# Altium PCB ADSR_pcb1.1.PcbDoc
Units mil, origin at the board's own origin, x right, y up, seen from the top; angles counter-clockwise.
Board outline 3150 x 1575 mil, 2 copper layers (Top Layer, Bottom Layer); 39 components, 29 nets, 111 pads, 15 vias.
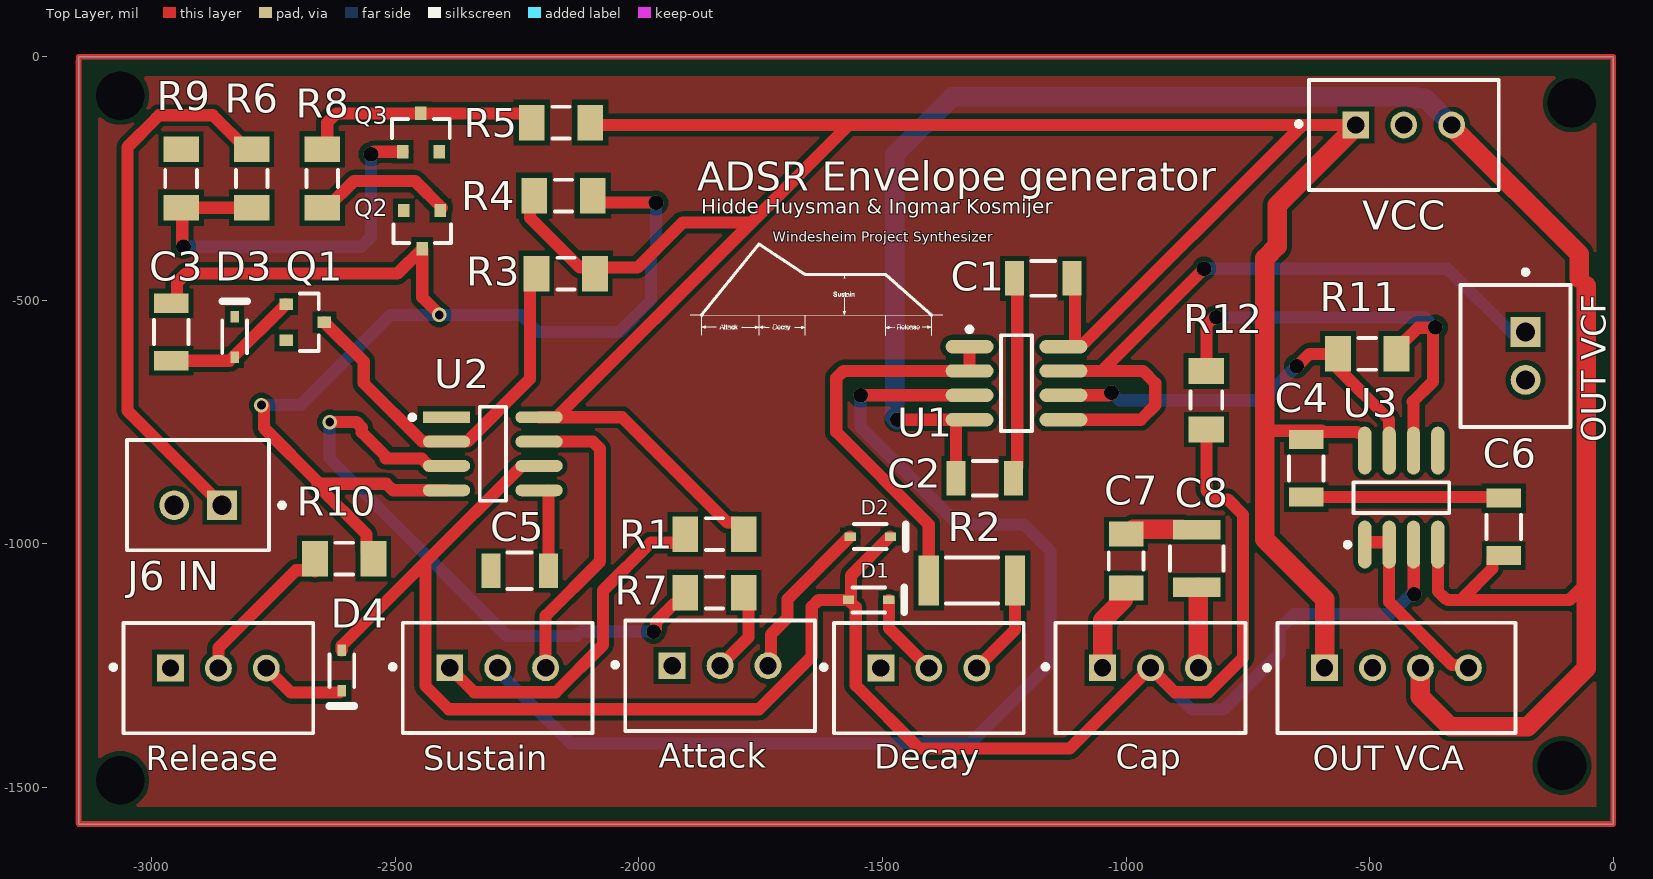
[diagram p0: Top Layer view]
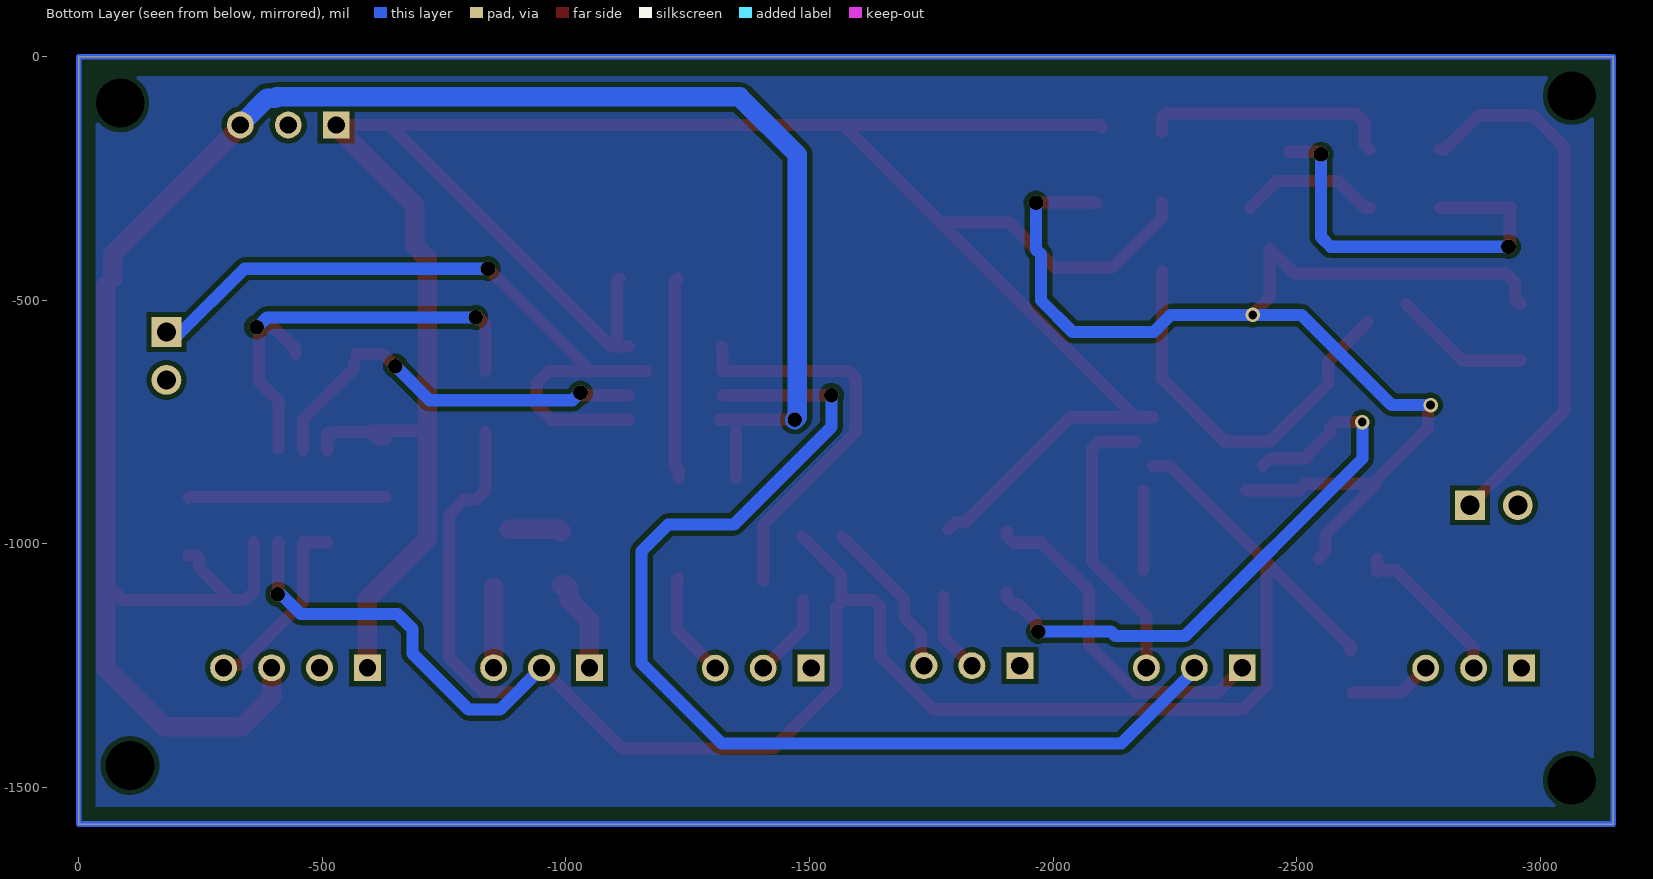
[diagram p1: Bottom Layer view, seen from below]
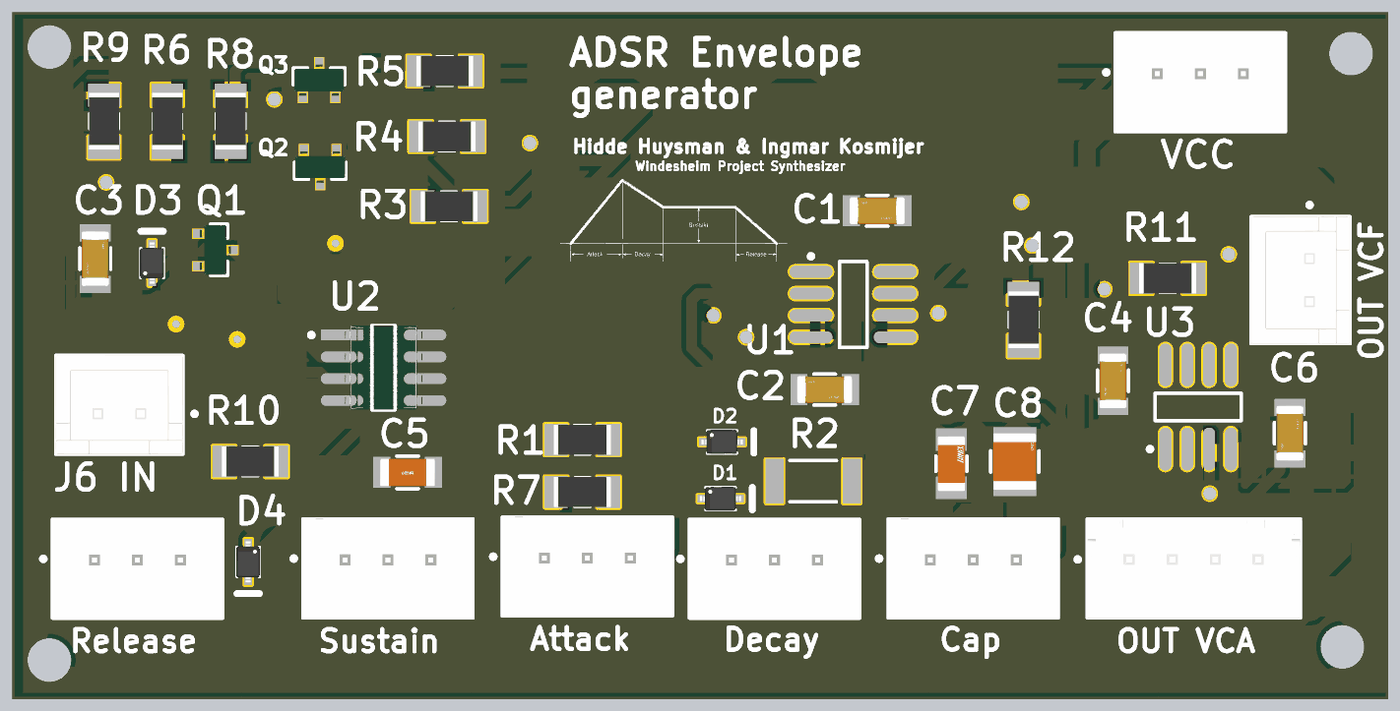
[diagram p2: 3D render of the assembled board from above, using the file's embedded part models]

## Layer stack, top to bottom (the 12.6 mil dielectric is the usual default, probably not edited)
Top Solder: solder mask 0.4, Solder Resist, Dk 3.5
Top Layer: signal copper 1.4
Dielectric 1: dielectric 12.6, FR-4, Dk 4.8
Bottom Layer: signal copper 1.4
Bottom Solder: solder mask 0.4, Solder Resist, Dk 3.5

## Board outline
-3150,-1575 -3150,0 0,0 0,-1575

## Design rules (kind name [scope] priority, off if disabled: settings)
Clearance [All] p1: gap=10 ignorepadtopadclearanceinfootprint=FALSE except(0: Arc-Hole Track-Hole SMDPad-Hole THPad-Hole Via-Hole Fill-Hole Poly-Hole Region-Hole Text-Hole)
HoleSize [IsVia] p1: absolutevalues=TRUE maxlimit=30 minlimit=12 maxpercent=80.000 minpercent=20.000
PolygonConnect [All] p1: connectstyle=Relief reliefconductorwidth=10 reliefentries=4 polygonreliefangle="90 Angle" airgapwidth=10
RoutingVias [All] p1: holewidth=28 width=50 viastyle="Through Hole" minholewidth=28 minwidth=50 maxholewidth=28 maxwidth=50
SolderMaskExpansion [All] p1: expansion=4 istentingtop=FALSE
Width [All] p1: maxlimit=40 minlimit=12 preferedwidth=25 minimp=50.000000 maximp=50.000000 favimp=50.000000
29 further rules are at their usual default settings.

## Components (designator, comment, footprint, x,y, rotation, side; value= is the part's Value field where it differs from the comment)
Attack "B3B-XH-A(LF)(SN)" FP-B3B-XH-A_LF_SN-MFG -1833.43,-1270.67 r0 top (schematic designator "J5 A")
C1 "CC1206KRX7R9BB103" FP-CC1206-1_25-MFG -1170,-455 r0 top value="10 nF"
C2 "CC1206KRX7R9BB103" FP-CC1206-1_25-MFG -1290,-865 r0 top value="10 nF"
C3 "CC1206KRX7R9BB103" FP-CC1206-1_25-MFG -2960,-565 r270 top value="10 nF"
C4 "CC1206KRX7R9BB103" FP-CC1206-1_25-MFG -630,-845 r270 top value="10 nF"
C5 "CC1206KKX5R9BB106" FP-CC1206-FD-MFG -2245,-1055 r180 top
C6 "CC1206KRX7R9BB103" FP-CC1206-1_25-MFG -225,-965 r90 top value="10 nF"
C7 "1206YC224K4T2A" FP-1206-L_3_2_0_2-W_1_6_0-IPC_B -1000,-1035 r90 top
C8 "12105C475K4T2A" FP-1210-L_3_3_0_4-W_2_5_0-MFG -855,-1030 r90 top
Cap "B3B-XH-A(LF)(SN)" FP-B3B-XH-A_LF_SN-MFG -950,-1275 r0 top (schematic designator "J4 Cap")
D1 "1N4148WS" DIOD-SOD323-2-A_V -1528.46,-1115 r0 top
D2 "1N4148WS" DIOD-SOD323-2-A_V -1525,-985 r0 top
D3 "1N4148WS" DIOD-SOD323-2-A_V -2830,-575 r90 top
D4 "1N4148WS" DIOD-SOD323-2-A_V -2610,-1260 r270 top
Decay "B3B-XH-A(LF)(SN)" FP-B3B-XH-A_LF_SN-MFG -1405,-1275.67 r0 top (schematic designator "J2 D")
"J6 IN" "B2B-XH-A(LF)(SN)" FP-B2B-XH-A_LF_SN-MFG -2905,-900 r180 top
"OUT VCA" "B4B-XH-A(LF)(SN)" FP-B4B-XH-A_LF_SN-MFG -445,-1275 r180 top
"OUT VCF" "B2B-XH-A(LF)(SN)" FP-B2B-XH-A_LF_SN-MFG -200.67,-614.21 r270 top (schematic designator "J9 OUT VCF")
Q1 "BC847,215" FP-SOT23-MFG -2685,-545 r0 top
Q2 "BC847,215" FP-SOT23-MFG -2445,-355 r270 top
Q3 "BC847,215" FP-SOT23-MFG -2447.6,-155.63 r90 top
R1 "Resistor 100k +/-1% 1206 250 mW" RESC3216X60X45ML15T20 -1845,-980 r0 top value=4.7k
R2 "CRCW2010100RFKEF" RESC2010(5025)_L -1316.42,-1075 r180 top value=1k
R3 "Resistor 100k +/-1% 1206 250 mW" RESC3216X60X45ML15T20 -2150.04,-445 r0 top value=4.7k
R4 "Resistor 100k +/-1% 1206 250 mW" RESC3216X60X45ML15T20 -2154.96,-285 r180 top value=4.7k
R5 "Resistor 100k +/-1% 1206 250 mW" RESC3216X60X45ML15T20 -2160,-135 r0 top value=4.7k
R6 "Resistor 100k +/-1% 1206 250 mW" RESC3216X60X45ML15T20 -2795,-250 r90 top value=10k
R7 "Resistor 100k +/-1% 1206 250 mW" RESC3216X60X45ML15T20 -1844.96,-1100 r180 top value=100
R8 "Resistor 100k +/-1% 1206 250 mW" RESC3216X60X45ML15T20 -2650,-250 r90 top value=10k
R9 "Resistor 100k +/-1% 1206 250 mW" RESC3216X60X45ML15T20 -2940,-250 r270 top value=100k
R10 "Resistor 100k +/-1% 1206 250 mW" RESC3216X60X45ML15T20 -2605,-1030 r0 top value=100
R11 "Resistor 100k +/-1% 1206 250 mW" RESC3216X60X45ML15T20 -505,-610 r0 top value=3k
R12 "Resistor 100k +/-1% 1206 250 mW" RESC3216X60X45ML15T20 -835,-705 r270 top value=4.7k
Release "B3B-XH-A(LF)(SN)" FP-B3B-XH-A_LF_SN-MFG -2863.43,-1275.67 r0 top (schematic designator "J8 R")
Sustain "B3B-XH-A(LF)(SN)" FP-B3B-XH-A_LF_SN-MFG -2290,-1275 r0 top (schematic designator "J3 S")
U1 "AD8066ARZ-R7" ADI-R-8_M -1225,-670 r0 top
U2 "NE555DR" FP-D0008A-IPC_A -2300,-815 r0 top
U3 "AD8066ARZ-R7" ADI-R-8_M -435,-905 r90 top
VCC "B3B-XH-A(LF)(SN)" FP-B3B-XH-A_LF_SN-MFG -430,-160.67 r0 top (schematic designator J1)

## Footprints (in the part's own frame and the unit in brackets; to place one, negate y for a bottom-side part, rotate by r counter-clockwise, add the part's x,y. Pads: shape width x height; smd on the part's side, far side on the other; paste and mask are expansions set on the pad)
ADI-R-8_M [mm] "SOIC, 8-Leads, Body 4.9x3.9mm, Pitch 1.27mm, IPC Low Density"
  oval 2.5x0.7 smd: 1(-2.45,1.905) 2(-2.45,0.635) 3(-2.45,-0.635) 4(-2.45,-1.905) 5(2.45,-1.905) 6(2.45,-0.635) 7(2.45,0.635) 8(2.45,1.905)
  silkscreen extent -2.57,-2.5 0.8,2.93, body extent -2,-2.5 2,2.5, height 1.75
DIOD-SOD323-2-A_V [mm] "SOD-323, 2-Leads, Body 1.7x1.3mm, Lead Span 2.5mm"
  rect 0.59x0.45 smd: 1(-1.055,0) 2(1.055,0)
  silkscreen extent -0.85,-0.65 1.85,0.65, body extent -1.24,-0.7 1.24,0.7, height 1.2
FP-1206-L_3_2_0_2-W_1_6_0-IPC_B [mil]
  rect 51.36x71.11 smd paste+0 mask+0: 1(-55.15,0) 2(55.15,0)
  silkscreen extent -18,-36 18,36, body extent -91,-45 91,45, height 10
FP-1210-L_3_3_0_4-W_2_5_0-MFG [mm]
  rect 1x2.5 smd paste+0 mask+0: 1(-1.5,0) 2(1.5,0)
  silkscreen extent -0.62,-1.4 0.62,1.4, body extent -2.1,-1.5 2.1,1.5, height 0.25
FP-B2B-XH-A_LF_SN-MFG [mm]
  rect 1.55x1.55 hole 1 paste-2539.97 mask+0: 1(-1.25,0.525)
  round 1.55 hole 1 paste-2539.97 mask+0: 2(1.25,0.525)
  silkscreen extent -4.5,-2.87 3.7,2.88, body extent -3.8,-2.98 3.8,2.98, height 0.25
FP-B3B-XH-A_LF_SN-MFG [mm]
  rect 1.4x1.4 hole 0.9 paste-2539.97 mask+0: 1(-2.5,0.525)
  round 1.4 hole 0.9 paste-2539.97 mask+0: 2(0,0.525) 3(2.5,0.525)
  silkscreen extent -5.6,-2.87 4.95,2.88, body extent -5.05,-2.98 5.05,2.98, height 0.25
FP-B4B-XH-A_LF_SN-MFG [mm]
  rect 1.4x1.4 hole 0.9 paste-2539.97 mask+0: 1(3.75,-0.525)
  round 1.4 hole 0.9 paste-2539.97 mask+0: 2(1.25,-0.525) 3(-1.25,-0.525) 4(-3.75,-0.525)
  silkscreen extent -6.2,-2.88 6.87,2.87, body extent -6.3,-2.98 6.3,2.98, height 0.25
FP-CC1206-1_25-MFG [mm]
  rect 1x1.8 smd paste+0 mask+0: 1(-1.5,0) 2(1.5,0)
  silkscreen extent -0.62,-0.9 0.63,0.9, body extent -2.2,-1.25 2.2,1.25, height 0.25
FP-CC1206-FD-MFG [mm]
  rect 1x1.8 smd paste+0 mask+0: 1(-1.5,0) 2(1.5,0)
  silkscreen extent -0.62,-0.95 0.62,0.95, body extent -2.32,-1.38 2.32,1.38, height 0.25
FP-D0008A-IPC_A [mil]
  rect 97.21x24.49 smd paste+0 mask+0: 1(-95.02,75)
  rrect100% 97.21x24.49 smd paste+0 mask+0: 2(-95.02,25) 3(-95.02,-25) 4(-95.02,-75) 5(95.02,-75) 6(95.02,-25) 7(95.02,25) 8(95.02,75)
  silkscreen extent -170,-97 27,97, body extent -163,-116 163,116, height 10
FP-SOT23-MFG [mm]
  rect 0.7x0.6 smd paste-1000 mask+0: 1(-1,0.95) 2(-1,-0.95) 3(1,0)
  silkscreen extent -0.27,-1.5 0.7,1.5, body extent -1.5,-1.65 1.5,1.65, height 0.25
RESC2010(5025)_L [mm] "Chip Resistor, Body 5.0x2.5mm, IPC High Density"
  rect 1.05x2.6 smd: 1(-2.25,0) 2(2.25,0)
  silkscreen extent -1.35,-1.2 1.35,1.2, body extent -2.6,-1.35 2.6,1.35, height 0.71
RESC3216X60X45ML15T20 [mm] "Chip Resistor, 2-Leads, Body 3.3x1.75mm, IPC Low Density"
  rect 1.35x1.85 smd: 1(-1.525,0) 2(1.525,0)
  silkscreen extent -0.45,-0.82 0.45,0.82, body extent -1.65,-0.87 1.65,0.87, height 0.6

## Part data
Attack Cap Decay Release Sustain VCC: library part CMP-17439-000014-3, "CONN HEADER VERT 3POS 2.5MM", Color=Natural, Contact Resistance=20mR, Current Rating=3A, Flammability Rating="UL94 V-0", Housing Color=White, Insulation Resistance=1GR, Max Operating Temperature=85°C, Max Voltage Rating (AC)=250V, Min Operating Temperature=-25°C
C1 C2 C3 C4 C6: library part CMP-1037-03511-2, "CAP CER 10000PF 50V X7R 1206", Capacitance="10 nF", Manufacturer=Yageo, Package=CC1206-1.25, Temperature="-55°C to +125°C", Temperature Characteristic=X7R, Temperature Coefficient=15%, Temperature Range High=+125°C, Temperature Range Low=-55°C, Tolerance=0.1, Voltage Rating="50 V"
C5: library part CMP-03422-001420-1, "CAP CER 10UF 50V X5R 1206", Capacitance=10uF, Case/Package=1206, Dielectric=X5R, Max Operating Temperature=85°C, Min Operating Temperature=-55°C, Tolerance=10%, Voltage Rating=50V
C7: library part CMP-04427-019066-1, "Automotive Ceramic Capacitor, 1206, 220nF, 10%, X7R, 15%, 16V", Capacitance=220nF, Case/Package=1206, Dielectric=X7R, Max Operating Temperature=125°C, Min Operating Temperature=-55°C, Tolerance=10%, Voltage Rating (DC)=16V
C8: library part CMP-04427-006002-1, "Automotive Ceramic Capacitor, 1210, 4.7uF, 10%, X7R, 15%, 50V", Capacitance=4.7uF, Case Code (Imperial)=1210, Case Code (Metric)=3225, Dielectric=X7R, Max Operating Temperature=125°C, Min Operating Temperature=-55°C, Package Quantity=1000, Ratings=AEC-Q200, Tolerance=10%, Voltage Rating=50V
D1 D2 D3 D4: library part CMP-004-00002-2, "Fast Switching Diode, 75 V, 0.3 A, -65 to 150 degC, 2-Pin SOD323, RoHS, Tape and Reel", Case/Package=SOD, Forward Current=300mA, Forward Voltage=1.25V, Manufacturer="Diodes Inc", Max Operating Temperature=150°C, Max Surge Current=2A, Min Operating Temperature=-65°C, Package Description="2-Pin Small Outline Diode, Body 1.7 x 1.3 mm", Package Quantity=3000, Package Reference=SOD323-2, Peak Reverse Current=1uA
"J6 IN" "OUT VCF": library part CMP-2000-05888-3, "CONN HEADER VERT 2POS 2.5MM", Color=Natural, Contact Resistance=20mR, Current Rating=3A, Housing Color=White, Insulation Resistance=1GR, Max Operating Temperature=85°C, Max Voltage Rating (AC)=250V, Min Operating Temperature=-25°C
"OUT VCA": library part CMP-17439-000250-1, "CONN HEADER VERT 4POS 2.5MM", Color=Natural, Contact Resistance=20mR, Current Rating=3A, Flammability Rating="UL94 V-0", Housing Color=White, Insulation Resistance=1GR, Max Operating Temperature=85°C, Max Voltage Rating (AC)=250V, Min Operating Temperature=-25°C, Package Quantity=500
Q1 Q2 Q3: library part CMP-14406-000009-1, "TRANS NPN 45V 0.1A SOT23", Ambient Temperature Range High=+150°C, Ambient Temperature Range Low=-65°C, Collector Base Voltage=50V, Collector Emitter Breakdown Voltage=45V, Collector Emitter Saturation Voltage=200mV, Emitter Base Voltage=6V, Manufacturer=Nexperia, Max Collector Current=100mA, Package=SOT23, Power Dissipation=250mW, Temperature="to +150°C"
R1 R3 R4 R5 R6 R7 R8 R9 R10 R11 R12: library part CMP-009-00025-5, "Chip Resistor, 100 KOhm, +/- 1%, 0.25 W, -55 to 155 degC, 1206 (3216 Metric)", Case/Package=1206, Max Operating Temperature=155°C, Min Operating Temperature=-55°C, Power=250mW, Tolerance=1%, Voltage Rating=200V
R2: library part CMP-009-00178-1, "Fixed Resistor, Metal Glaze/thick Film, 0.75W, 100ohm, 400V, 1% +/-Tol, 100ppm/Cel, Surface Mount, 2010", Case/Package=2010, Max Operating Temperature=155°C, Min Operating Temperature=-55°C, Power=750mW, Tolerance=1%
U1 U3: library part CMP-0384-01346-2, "Double Channel Low Power Operational Amplifier, 145 MHz BW, 180 V/us SR, Industrial, 8-pin SOIC (R-8), Reel", Amplifiers Per Package=2, Generic Part Number=AD8066, Input Bias Current=2pA, Input Offset Voltage=400uV, Manufacturer="Analog Devices"
U2: library part CMP-1685-00007-2, "IC OSC SGL TIMER 100KHZ 8-SOIC", Case/Package=SOIC, Frequency=100kHz, High Level Output Current=-200mA, Low Level Output Current=200mA, Max Operating Temperature=70°C, Max Supply Voltage=16V, Min Operating Temperature=0°C, Min Supply Voltage=4.5V, Operating Supply Current=10mA, Package Quantity=2500, Quiescent Current=15mA

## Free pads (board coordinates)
  round 60 hole 100 unplated: 31(-105,-1455) 33(-3065,-1485) 34(-3065,-80) 35(-85,-95)

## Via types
v1: diameter 30, hole 30, Top Layer to Bottom Layer, 12 vias
v2: diameter 30, hole 18, Top Layer to Bottom Layer, 3 vias

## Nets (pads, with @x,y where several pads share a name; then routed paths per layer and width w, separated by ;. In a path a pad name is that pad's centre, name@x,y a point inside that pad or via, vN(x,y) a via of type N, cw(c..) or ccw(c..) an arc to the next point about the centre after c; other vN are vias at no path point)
+12: "OUT VCA.1" C1.2 C4.1 R1.2 R3.2 R4.2 R5.2 U1.8 U2.8 U3.8 VCC.1 | length 5844.4
  Top Layer w25: R4.2@-2223.58,-300 -2223.58,-330.51 -2121.2,-432.89 -2002.89,-432.89 -1910,-340 -1769.12,-340 ; U2.8 U2.8@-2169.12,-740 ; R5.2@-2100,-145 -2095,-140 -1569.12,-140 ; R1.2@-1785,-970.12 -1799.04,-956.08 -1818.92,-956.08 -2035,-740 U2.8@-2169.12,-740 ; U1.8 -1093.11,-595 -638.11,-140 ; C1.2 -1105,-460.94 U1.8@-1105,-593.82 ; -715,-767.62 -614.06,-767.62 C4.1@-598.31,-767.62 ; C4.1 -614.25,-785.94 -598.31,-770 -525.92,-770 -523.3,-772.62 -511.18,-772.62 -510,-773.8 U3.8 ; VCC.1 -638.11,-140 ; U2.8@-2169.12,-740 -1769.12,-340 ; -1769.12,-340 -1569.12,-140 ; -1569.12,-140 -638.11,-140
  Top Layer w40: -592.64,-1254.33 -592.64,-1113.32 -715,-990.95 -715,-767.62 -715,-413.78 -690,-388.78 -690,-305 VCC.1@-526.71,-141.71
-12: "OUT VCA.3" C2.1 C6.1 U1.4 U3.4 VCC.3 | length 4294
  Top Layer w25: v1(-1470,-745) U1.4@-1348.85,-745 ; C2.1 -1349.06,-746.18 -1348.36,-745.49 U1.4@-1348.85,-745 ; U1.4@-1315,-745 U1.4 U1.4@-1348.85,-745 ; U3.4@-360,-996.46 U3.4 -360,-1097.14 -345.36,-1111.78 ; -339.52,-1115 -312.73,-1115 ; C6.1 -240.75,-1024.06 -247.93,-1031.24 -247.93,-1050.21 -312.73,-1115 ; -69.64,-455 -55,-469.64 ; -55,-1080 -90,-1115 -312.73,-1115
  Top Layer w40: -395.79,-1254.33 -395.79,-1314.21 -335,-1375 -175,-1375 -55,-1255 -55,-1080 -55,-469.64 ; VCC.3@-329.75,-145.25 -69.64,-405.36 -69.64,-455
  Bottom Layer w40: v1(-1470,-745) -1475,-740 -1475,-200.87 -1356.57,-82.44 -406.16,-82.44 -403.6,-85 -386.57,-85 VCC.3
GND: "J6 IN.2" "OUT VCA.2" "OUT VCF.2" Attack.1 C1.1 C2.2 C4.2 C5.2 C6.2 C7.2 C8.2 D3.2 Decay.1 Q1.2 Q2.2 Q3.2 R9.1 Release.1 U2.1 U3.5 VCC.2 | length 929.7
  Top Layer w25: C2.2 -1230.94,-849.25 -1223.28,-841.59 -1223.28,-460.78 C1.1 ; C4.2 -226.89,-904.06 C6.2
  Top Layer w40: C7.2@-990,-974.7 -984.85,-969.56 -885.29,-969.56 C8.2@-884.21,-970.63
NetC3_1: C3.1 Q2.3 R4.1 R10.2 U2.4 | length 2654.1
  Top Layer w25: C3.1 -2955.59,-505.94 -2948.4,-498.76 -2948.4,-463.4 -2930,-445 -2495.63,-445 Q2.3 -2445,-493.65 -2410,-528.65 v2(-2410,-530) ; v2(-2775,-715) v2@-2772.5,-717.5 ; v2@-2770,-715 -2770,-761.93 -2655.51,-876.42 -2518.58,-876.42 -2505,-890 U2.4 ; -2659.55,-880.45 -2559.04,-980.96 -2559.04,-1015.93 R10.2 ; R4.1@-2088.54,-300 -2087.59,-299.04 -1965.96,-299.04 v1(-1965,-300)
  Bottom Layer w25: v2(-2775,-715) -2695,-715 -2510,-530 v2(-2410,-530) -2241.82,-530 -2206.82,-565 -2040,-565 -1975,-500 -1975,-405.41 -1965,-395.41 v1(-1965,-300)
NetC3_2: C3.2 D3.1 Q1.1 | length 284.2
  Top Layer w25: C3.2 -2840.83,-624.06 -2725.65,-508.88 -2725.65,-508.29 -2724.96,-507.6 Q1.1
NetC5_1: C5.1 U2.5 | length 164.7
  Top Layer w25: C5.1 U2.5@-2185.94,-890.25
NetC7_1: C7.1 Cap.1 | length 199.3
  Top Layer w40: Cap.1 -1048.43,-1157.17 -1005.56,-1114.29 -1005.56,-1090.68 -999.87,-1085 C7.1@-990,-1085
NetC8_1: C8.1 Cap.3 | length 165
  Top Layer w40: Cap.3 C8.1@-851.57,-1089.37
NetD1_1: Cap.2 D1.1 D2.2 D4.1 R12.2 U2.6 U3.3 | length 4498.2
  Top Layer w25: D4.1 -2610,-1209.17 -2438.48,-1037.65 ; U2.6 -2240.83,-840 -2438.48,-1037.65 ; D1.1@-1580,-1115 -1631.54,-1115 -1645.4,-1128.86 -1645.4,-1231.19 -1753.59,-1339.39 -2390.3,-1339.39 -2438.48,-1291.21 -2438.48,-1037.65 ; D2.2@-1485,-985 -1565,-1065 -1565,-1115 D1.1 -1555.15,-1129.85 -1555.15,-1290.21 -1425.36,-1420 -1115.67,-1420 -950.67,-1255 Cap.2@-950,-1255 ; Cap.2@-950,-1246.18 Cap.2 -899.94,-1304.39 -830.84,-1304.39 -760,-1233.55 -760,-940 -790.99,-909.01 -816.22,-909.01 -834.96,-890.27 R12.2@-834.96,-770 ; U3.3@-410,-996.46 -409.51,-996.95 -409.51,-1102.64 v1(-408.57,-1103.57)
  Bottom Layer w25: Cap.2@-950,-1255 -865,-1340 -800,-1340 -685,-1225 -685,-1174.64 -654.07,-1143.71 -455.48,-1143.71 -415.34,-1103.57 v1(-408.57,-1103.57)
NetD1_2: D1.2 Decay.2 | length 173.9
  Top Layer w25: D1.2 -1486.93,-1173.07 Decay.2
NetD2_1: Attack.3 D2.1 | length 334.8
  Top Layer w25: Attack.3 -1729.24,-1244.24 -1729.24,-1186.09 -1695,-1151.85 -1695,-1113.46 D2.1
NetD4_2: D4.2 Release.3 | length 170.7
  Top Layer w25: Release.3 -2715,-1305 D4.2@-2615,-1305
"NetJ2 D_3": Decay.3 R2.1 | length 218.5
  Top Layer w25: Decay.3 -1227.84,-1176.26 R2.1 -1227.84,-1072.16 R2.1@-1230,-1070
"NetJ3 S_1": R1.1 Sustain.1 | length 711
  Top Layer w25: Sustain.1 -2338.36,-1304.39 -2170.84,-1304.39 -2073.8,-1207.35 -2073.8,-1095.72 -1975.77,-997.7 -1919.11,-997.7 -1905,-983.58 R1.1@-1905,-975
"NetJ3 S_2": Sustain.2 U1.3 | length 2284.6
  Top Layer w25: v1(-1545,-695) U1.3
  Bottom Layer w25: Sustain.2@-2290,-1255 -2290,-1260 -2140,-1410 -1320,-1410 -1155,-1245 -1155,-1015 -1210,-960 -1345,-960 -1545,-760 v1(-1545,-695)
"NetJ3 S_3": Sustain.3 U2.7 | length 590.8
  Top Layer w25: Sustain.3 -2191.57,-1147.57 -2080,-1035.99 -2080,-804.64 -2094.64,-790 U2.7@-2168.87,-790
"NetJ5 A_2": Attack.2 R7.1 | length 166.3
  Top Layer w25: Attack.2 -1775,-1191.57 R7.1@-1775,-1107.95
"NetJ6 IN_1": "J6 IN.1" R6.2 | length 1119.9
  Top Layer w25: -2990,-125 -3050,-185 -3050,-726.46 -2855.79,-920.67 ; -2985,-120 -2874.8,-120 -2804.84,-189.96 R6.2
"NetJ8 R_2": R10.1 Release.2 | length 348.3
  Top Layer w25: Release.2 -2863.21,-1254.78 -2863.21,-1213.21 -2703.92,-1053.92 -2679.11,-1053.92 -2665.04,-1039.84 R10.1 R10.1@-2665.04,-1056.61
"NetJ9 OUT VCF_1": "OUT VCF.1" U1.5 U1.7 | length 1471.3
  Top Layer w25: U1.7@-1164.67,-645 U1.7 -1050,-645 ; U1.5 -970,-745 -939.74,-714.74 ; -940,-710 -940,-670 -965,-645 -1050,-645 ; v1(-840,-435) -1050,-645
  Bottom Layer w25: v1(-840,-435) -340.12,-435 -200.12,-575 -200,-575
"NetOUT VCA_4": "OUT VCA.4" U3.1 U3.2 | length 392.2
  Top Layer w25: U3.1@-510,-996.46 -461.18,-996.46 -460,-995.27 U3.2@-460,-995 ; U3.2@-460,-996.46 -460,-1119.32 -330.76,-1248.57 -303.12,-1248.57 -297.36,-1254.33
NetQ1_3: Q1.3 R3.1 U2.2 | length 824.4
  Top Layer w25: Q1.3 -2645.04,-545 -2644.35,-545.69 -2644.35,-546.28 -2565,-625.63 -2565,-670 -2445,-790 U2.2 -2394.77,-789.75 -2352.1,-789.75 -2223.58,-661.23 R3.1@-2223.58,-440
NetQ2_1: Q2.1 R8.1 | length 290.6
  Top Layer w25: R8.1 -2640.16,-310.04 -2585.12,-255 -2460,-255 Q2.1@-2405,-310
NetQ3_1: Q3.1 R6.1 R9.2 | length 856.4
  Top Layer w25: R9.2 R9.2@-2937.5,-310.04 ; v1(-2935,-390) -2937.5,-387.5 R9.2@-2937.5,-310.04 ; R6.1 R6.1 R9.2@-2937.5,-310.04 ; v1(-2550,-200) -2548.65,-200 -2543.65,-195 Q3.1
  Bottom Layer w25: v1(-2935,-390) -2570,-390 -2550,-370 v1(-2550,-200)
NetQ3_3: Q3.3 R5.1 R8.2 | length 515.2
  Top Layer w25: R8.2 -2640,-179.96 -2640,-135 ; -2638.59,-133.59 -2621.26,-116.26 Q3.3 -2231.81,-116.26 -2223.58,-124.49 R5.1@-2223.58,-155
NetR2_2: R2.2 U1.1 U1.2 | length 824.4
  Top Layer w25: R2.2 -1405,-960 -1595,-770 -1595,-659.64 -1580.36,-645 U1.2 -1321.46,-596.18 -1320.27,-595 U1.1@-1320,-595
NetR7_2: R7.2 U2.3 | length 1252.2
  Top Layer w25: v2(-2635,-750) -2580,-750 -2569.14,-760.86 -2569.14,-770.86 -2520,-820 ; -2520,-825 -2445.88,-825 U2.3@-2431.13,-839.75 ; v1(-1970,-1180) -1970,-1178.65 -1965.22,-1173.86 -1965.22,-1160.22 -1928.92,-1123.92 -1919.07,-1123.92 -1905,-1109.84 R7.2
  Bottom Layer w25: v2(-2635,-750) -2635,-825 -2270.83,-1189.17 -2128.38,-1189.17 -2119.21,-1180 v1(-1970,-1180)
NetR11_1: R11.1 U1.6 U3.7 | length 828.2
  Top Layer w25: U1.6 -1036.35,-695 -1031.35,-690 v1(-1030,-690) ; v1(-650,-635) -648.81,-635 -623.81,-610 R11.1@-570,-610 ; R11.1@-565.08,-630 -565.08,-639.84 -460,-744.92 U3.7
  Bottom Layer w25: v1(-1030,-690) -1028.65,-690 -1013.65,-705 -720,-705 v1(-650,-635)
NetR11_2: R11.2 R12.1 U3.6 | length 949.1
  Top Layer w25: R12.1 -835,-550 v1@-820,-535 ; R11.2 -444.96,-600.16 -400.92,-556.12 -366.12,-556.12 v1(-365,-555) ; U3.6@-410,-805 -410,-710 -411.62,-708.38 -370,-666.76 v1@-370,-555
  Bottom Layer w25: v1(-815,-535) -386.35,-535 -367.31,-554.04 v1@-367.31,-555

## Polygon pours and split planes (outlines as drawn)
no net on Top Layer "NONET_L01_P001" (solid, pour order 1): -3110,-40 -3110,-1540 -35,-1540 -35,-40
GND on Top Layer "Top Layer-GND" (solid, shelved, pour order 0): -3151.19,-2.72 -3156.19,-7.72 -3156.19,-1572.72 -6.19,-1572.72 -1.19,-1577.72 -1.19,-2.72
no net on Bottom Layer "NONET_L02_P002" (solid, pour order 2): -3110,-40 -3110,-1540 -35,-1540 -35,-40

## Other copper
Multi-Layer:
  the board outline again, w12

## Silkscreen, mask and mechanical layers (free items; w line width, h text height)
Top Overlay:
  drawing of 30 lines, arcs and shapes, not listed
  text "ADSR Envelope generator" at -1880,-274.75 h60
  text "Hidde Huysman & Ingmar Kosmijer" at -1872,-322 h30
  text "Windesheim Project Synthesizer" at -1725,-380 h20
